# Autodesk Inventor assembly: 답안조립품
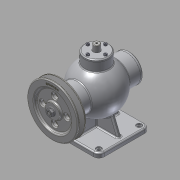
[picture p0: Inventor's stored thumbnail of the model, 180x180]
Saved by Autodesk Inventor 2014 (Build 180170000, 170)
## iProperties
Created: 2015-10
Part Number: 답안조립품
Document SubType Name: Assembly
Designer: youjin10
Author: youjin10
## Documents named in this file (19)
- C:\Users\youjin10\Desktop\451010V1008\답안조립품.iam
- C:\Users\youjin10\Desktop\451010V1008\본체.ipt
- C:\Users\youjin10\Desktop\451010V1008\앞커버.ipt
- C:\Users\youjin10\Desktop\451010V1008\볼트 M4 x 16.ipt
- C:\Users\youjin10\Desktop\451010V1008\오일실 15 30 7.ipt
- C:\Users\youjin10\Desktop\451010V1008\뒤커버.ipt
- C:\Users\youjin10\Desktop\451010V1008\상부커버.ipt
- C:\Users\youjin10\Desktop\451010V1008\볼트 M 4 x 12.ipt
- C:\Users\youjin10\Desktop\451010V1008\베어링- 6202.ipt
- KS B 2023 - 6202 - 15 x 35 x 11 - 7.8.ipt
- C:\Users\youjin10\Desktop\451010V1008\편심축.ipt
- C:\Users\youjin10\Desktop\451010V1008\부시.ipt
- C:\Users\youjin10\Desktop\451010V1008\키 4 x 4 x 12.ipt
- C:\Users\youjin10\Desktop\451010V1008\V-벨트풀리.ipt
- C:\Users\youjin10\Desktop\451010V1008\너트 M8.ipt
- C:\Users\youjin10\Desktop\451010V1008\멈춤링- 15 x 1.ipt
- C:\Users\youjin10\Desktop\451010V1008\멈춤링- 35x1.6.ipt
- KS B 1336 - 35x1.6.ipt
- C:\Users\youjin10\Desktop\451010V1008\슬라이드.ipt
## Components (16 placed, 5 different names)
1. KS B 2023 - 6202 - 15 x 35 x 11 - 7.8:1 — Mate:14, Mate:15, Mate:16, Mate:17, Angle:1
2. KS B 2023 - 6202 - 15 x 35 x 11 - 7.8:2 — Mate:12, Mate:13, Angle:2
3. V-벨트풀리:1 — Mate:23, Mate:24, Mate:25, Mate:26
4. KS B 1336 - 35x1.6:1 — Mate:30, Mate:31, Angle:6
5. ISO 4762 M4 x 16:1 — Insert:1
6. ISO 4762 M4 x 16:2
7. ISO 4762 M4 x 16:3
8. ISO 4762 M4 x 16:4
9. ISO 4762 M4 x 16:5 — Insert:2
10. ISO 4762 M4 x 16:6
11. ISO 4762 M4 x 16:7
12. ISO 4762 M4 x 16:8
13. KS B 1021 - 에 따름 ISO 1207 - 미터 A  M 4 x 12:1 — Insert:3
14. KS B 1021 - 에 따름 ISO 1207 - 미터 A  M 4 x 12:2
15. KS B 1021 - 에 따름 ISO 1207 - 미터 A  M 4 x 12:3
16. KS B 1021 - 에 따름 ISO 1207 - 미터 A  M 4 x 12:4
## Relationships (18: Mate 12, Insert 3, Angle 3)
- Insert:1: ISO 4762 M4 x 16:1
- Insert:2: ISO 4762 M4 x 16:5
- Insert:3: KS B 1021 - 에 따름 ISO 1207 - 미터 A  M 4 x 12:1
- Mate:12: KS B 2023 - 6202 - 15 x 35 x 11 - 7.8:2
- Mate:13: KS B 2023 - 6202 - 15 x 35 x 11 - 7.8:2
- Mate:14: KS B 2023 - 6202 - 15 x 35 x 11 - 7.8:1
- Mate:15: KS B 2023 - 6202 - 15 x 35 x 11 - 7.8:1
- Mate:16: KS B 2023 - 6202 - 15 x 35 x 11 - 7.8:1
- Mate:17: KS B 2023 - 6202 - 15 x 35 x 11 - 7.8:1
- Mate:23: V-벨트풀리:1
- Mate:24: V-벨트풀리:1
- Mate:25: V-벨트풀리:1
- Mate:26: V-벨트풀리:1
- Mate:30: KS B 1336 - 35x1.6:1
- Mate:31: KS B 1336 - 35x1.6:1
- Angle:1: KS B 2023 - 6202 - 15 x 35 x 11 - 7.8:1
- Angle:2: KS B 2023 - 6202 - 15 x 35 x 11 - 7.8:2
- Angle:6: KS B 1336 - 35x1.6:1
